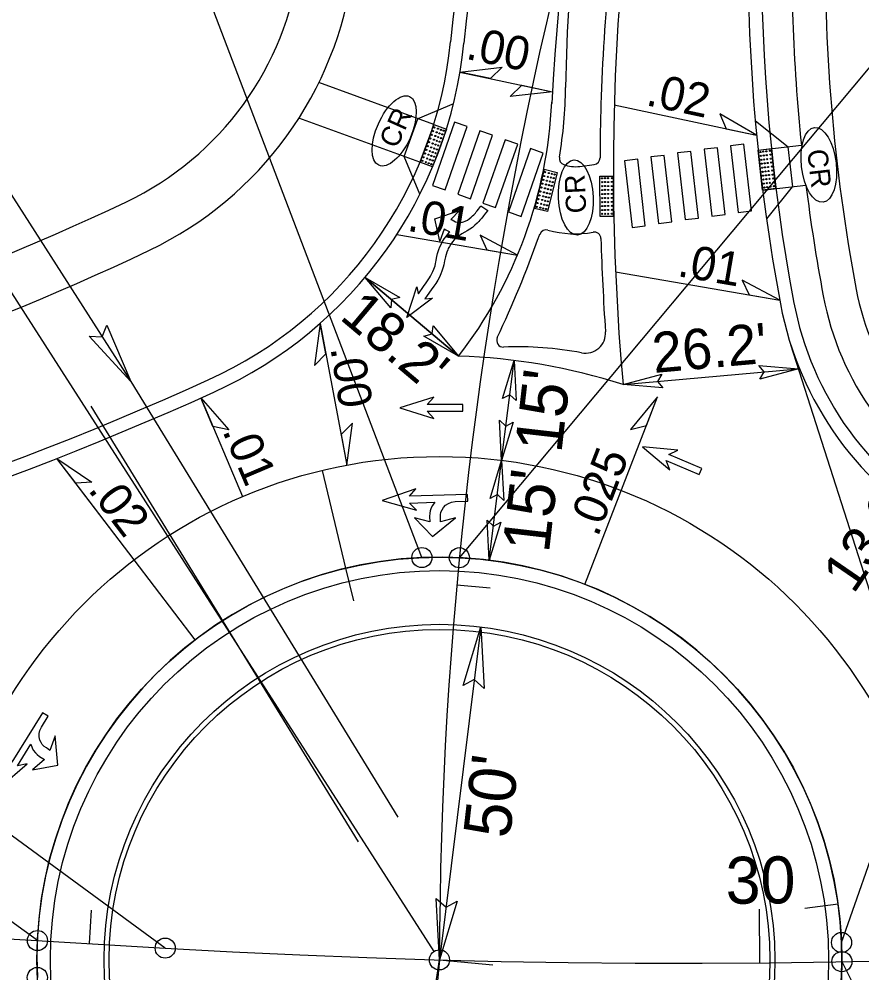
# Model space of a CAD drawing. Extents: x 2010838 to 2015151, y 441905 to 447792.
# Drawn here: x 2013125.6 to 2013251.3, y 444916.5 to 445058.6 of the extents above; entities that cross this region are included whole.
import ezdxf

# ---------------------------------------------------------------- set-up
doc = ezdxf.new("R2010")
doc.units = 0
for name, color, linetype in [('1-BUFFER', 7, 'Continuous'), ('A-Wall-Abov', 7, 'Continuous'), ('A-Wall-Blow', 7, 'Continuous'), ('A-Wall-Comp', 7, 'Continuous'), ('C-Building', 7, 'Continuous'), ('C-CURB STOPS', 7, 'Continuous'), ('C-EOP 1', 7, 'Continuous'), ('C-Grave Plots', 7, 'Continuous'), ('CLRD', 7, 'Continuous'), ('DEED', 7, 'Continuous'), ('Default_10ft_LIDAR_Contou', 7, 'Continuous'), ('Default_2FT_LIDAR_Contour', 7, 'Continuous'), ('HATCH', 7, 'Continuous'), ('s-Existing Major', 7, 'Continuous'), ('S-Existing Minor', 7, 'Continuous'), ('S-overhead electric', 7, 'Continuous'), ('TEXT-LG', 7, 'Continuous'), ('TEXT-MED', 7, 'Continuous'), ('X3', 7, 'Continuous'), ('X4', 7, 'Continuous')]:
    doc.layers.add(name, color=color, linetype=linetype)

msp = doc.modelspace()

# ---------------------------------------------------------------- linework, layer by layer
at = {"layer": '1-BUFFER'}
for centre, radius, start, end in [((2013121.83, 445072.89), 46, 295.4749, 352.5631), ((2013121.83, 445072.89), 54, 295.4749, 352.5631), ((2012983.33, 445363.58), 368, 266.6264, 295.4749), ((2012983.33, 445363.58), 376, 266.6264, 295.4749)]:
    msp.add_arc(centre, radius, start, end, dxfattribs=at)
at = {"layer": 'A-Wall-Abov'}
for points in [[(2013183.41, 445014.1), (2013184.89, 445018.66), (2013185.13, 445017.69), (2013185.14, 445017.65), (2013185.91, 445018.73), (2013186.3, 445019.29), (2013186.48, 445019.55), (2013186.78, 445020.01), (2013186.96, 445020.28), (2013187.06, 445020.46), (2013187.31, 445020.95), (2013187.45, 445021.29), (2013187.54, 445021.54), (2013187.62, 445021.83), (2013187.7, 445022.14), (2013187.75, 445022.34), (2013187.81, 445022.64), (2013187.91, 445023.22), (2013188.01, 445023.64), (2013188.1, 445023.94), (2013188.19, 445024.23), (2013188.36, 445024.65), (2013188.52, 445025), (2013188.74, 445025.43), (2013189, 445025.83), (2013189.23, 445026.15), (2013189.41, 445026.38), (2013189.55, 445026.54), (2013189.85, 445026.85), (2013189.67, 445026.92), (2013189.4, 445027.05), (2013189.24, 445027.13), (2013188.98, 445027.28), (2013188.34, 445025.46), (2013187.57, 445028.81), (2013191.26, 445030.05), (2013190, 445028.73), (2013190.16, 445028.64), (2013190.44, 445028.5), (2013190.69, 445028.38), (2013190.93, 445028.31), (2013191.18, 445028.26), (2013191.39, 445028.25), (2013191.71, 445028.29), (2013191.89, 445028.34), (2013192.12, 445028.44), (2013192.47, 445028.62), (2013192.73, 445028.81), (2013192.99, 445029.04), (2013193.21, 445029.24), (2013193.41, 445029.43), (2013193.63, 445029.67), (2013193.77, 445029.83), (2013193.92, 445030.01), (2013194.1, 445030.24), (2013194.24, 445030.43), (2013194.4, 445030.66), (2013194.47, 445030.77), (2013195.47, 445030.06), (2013195.17, 445029.65), (2013194.87, 445029.27), (2013194.6, 445028.93), (2013194.32, 445028.61), (2013194.13, 445028.39), (2013193.9, 445028.15), (2013193.58, 445027.85), (2013193.21, 445027.54), (2013192.82, 445027.26), (2013192.43, 445027.03), (2013192.05, 445026.83), (2013191.64, 445026.58), (2013191.25, 445026.32), (2013190.78, 445025.95), (2013190.47, 445025.67), (2013190.22, 445025.37), (2013189.96, 445025.02), (2013189.76, 445024.7), (2013189.6, 445024.39), (2013189.51, 445024.17), (2013189.39, 445023.82), (2013189.19, 445023.15), (2013189.03, 445022.53), (2013188.91, 445021.98), (2013188.84, 445021.63), (2013188.8, 445021.45), (2013188.66, 445021), (2013188.51, 445020.6), (2013188.29, 445020.14), (2013188.03, 445019.68), (2013187.74, 445019.2), (2013187.45, 445018.79), (2013187.06, 445018.24), (2013186.45, 445017.37), (2013186.12, 445016.9), (2013187.22, 445017)], [(2013187.45, 444999.08), (2013186.45, 445000.16), (2013191.78, 445000.15), (2013191.78, 445001.15), (2013186.45, 445001.16), (2013187.45, 445002.24), (2013182.37, 445000.66)], [(2013222.6, 444991.41), (2013222.1, 444992.8), (2013227, 444990.7), (2013227.4, 444991.62), (2013222.49, 444993.72), (2013223.84, 444994.32), (2013218.55, 444994.86)], [(2013192.47, 444987.74), (2013183.81, 444987.47), (2013184.78, 444988.59), (2013179.74, 444986.85), (2013184.87, 444985.42), (2013183.84, 444986.47), (2013187.61, 444986.59), (2013187.26, 444986.12), (2013187.06, 444985.76), (2013186.92, 444985.31), (2013186.85, 444984.94), (2013186.8, 444984.47), (2013186.84, 444983.65), (2013184.57, 444984.25), (2013187.24, 444981.49), (2013190.66, 444984.26), (2013188.43, 444983.69), (2013188.42, 444984.34), (2013188.42, 444984.73), (2013188.51, 444985.12), (2013188.67, 444985.46), (2013188.86, 444985.8), (2013189.2, 444986.15), (2013189.62, 444986.41), (2013190.08, 444986.59), (2013190.61, 444986.69), (2013192.5, 444986.74)]]:
    msp.add_lwpolyline(points, close=True, dxfattribs=at)
msp.add_lwpolyline([(2013122.78, 444944.14), (2013126.81, 444947.62), (2013125.37, 444947.34), (2013127.36, 444950.55), (2013127.55, 444949.99), (2013127.74, 444949.63), (2013128.04, 444949.26), (2013128.31, 444949), (2013128.67, 444948.7), (2013129.38, 444948.28), (2013127.63, 444946.72), (2013131.4, 444947.42), (2013130.98, 444951.8), (2013130.22, 444949.62), (2013129.68, 444949.98), (2013129.36, 444950.19), (2013129.08, 444950.48), (2013128.89, 444950.81), (2013128.71, 444951.15), (2013128.61, 444951.62), (2013128.62, 444952.13), (2013128.73, 444952.6), (2013128.94, 444953.1), (2013129.95, 444954.7), (2013129.1, 444955.23), (2013124.52, 444947.87)], dxfattribs=at)
at = {"layer": 'A-Wall-Blow'}
for p, q in [((2013191.34, 445050.68), (2013205.11, 445047.75)), ((2013214.35, 445045.78), (2013235.55, 445041.27)), ((2013181.94, 445026.49), (2013199.91, 445023.41)), ((2013214.54, 445020.89), (2013239, 445016.69)), ((2013170.51, 445013.24), (2013174.47, 444992.11)), ((2013152.69, 445002.12), (2013158.94, 444987.42)), ((2013209.96, 444974.34), (2013220.8, 445002.31)), ((2013142.78, 444978.02), (2013131.25, 444993.12)), ((2013170.8, 444991.33), (2013174.3, 444976.74)), ((2013151.88, 444966.09), (2013133.68, 444989.94))]:
    msp.add_line(p, q, dxfattribs=at)
at = {"layer": 'A-Wall-Comp'}
for points in [[(2013191.34, 445050.68), (2013197.63, 445051.39), (2013195.87, 445049.72)], [(2013205.11, 445047.75), (2013198.82, 445047.04), (2013200.58, 445048.71)], [(2013235.55, 445041.27), (2013230.1, 445044.47), (2013231.03, 445042.23)], [(2013199.91, 445023.41), (2013194.34, 445026.39), (2013195.35, 445024.19)], [(2013239, 445016.69), (2013233.43, 445019.68), (2013234.45, 445017.47)], [(2013170.51, 445013.24), (2013169.65, 445006.98), (2013171.36, 445008.7)], [(2013152.69, 445002.12), (2013156.88, 444997.38), (2013154.5, 444997.86)], [(2013220.8, 445002.31), (2013216.77, 444997.44), (2013219.13, 444998)], [(2013174.47, 444992.11), (2013175.33, 444998.38), (2013173.61, 444996.66)], [(2013131.25, 444993.12), (2013136.48, 444989.56), (2013134.06, 444989.44)]]:
    msp.add_lwpolyline(points, close=True, dxfattribs=at)
at = {"layer": 'C-Building'}
for p, q in [((2013174.3, 444976.74), (2013175.46, 444971.88)), ((2013190.87, 444974.28), (2013195.85, 444973.83)), ((2013136.12, 444920.83), (2013136.41, 444925.82)), ((2013136.12, 444920.83), (2013136.41, 444925.82)), ((2013247.7, 444926.73), (2013242.75, 444926.04))]:
    msp.add_line(p, q, dxfattribs=at)
at = {"layer": 'C-CURB STOPS'}
msp.add_line((2013209.19, 445036.62), (2013211.35, 445036.91), dxfattribs=at)
msp.add_circle((2013188.28, 444918.4), 58, dxfattribs=at)
for centre, radius, start, end in [((2013432.07, 445045.8), 225, 165.9339, 179.3398), ((2013462.25, 445038.81), 250, 169.3674, 178.3799), ((2013138.34, 445049.19), 68.75, 350.6175, 359.3398), ((2013563.46, 445035.95), 351.25, 178.3799, 179.6818), ((2013207.16, 445037.82), 1, 170.6175, 250.0381), ((2013211.22, 445037.9), 1, 277.6992, 359.6818), ((2013208.52, 445041.58), 5, 250.0381, 277.6992), ((2013138.34, 445049.19), 68.75, 340.2993, 340.736), ((2013204.19, 445026.17), 1, 74.2692, 160.736), ((2013208.52, 445041.58), 15, 254.2692, 280.1946), ((2013211.36, 445025.83), 1, 1.6461, 100.1946), ((2013047.54, 445081.7), 165.19, 334.7102, 340.2993), ((2013563.46, 445035.95), 351.25, 181.6461, 183.91), ((2013197.81, 445010.7), 1, 154.7102, 272.3391), ((2013210.04, 445011.79), 3, 259.2155, 3.91), ((2013199.93, 444958.74), 51, 79.2155, 92.3391)]:
    msp.add_arc(centre, radius, start, end, dxfattribs=at)
at = {"layer": 'C-EOP 1'}
for p, q in [((2013236.05, 444917.96), (2013235.98, 444925.96)), ((2013236.05, 444917.96), (2013235.98, 444925.96)), ((2013188.28, 444918.4), (2013196.25, 444917.68))]:
    msp.add_line(p, q, dxfattribs=at)
at = {"layer": 'CLRD'}
for p, q in [((2011239.41, 445032.63), (2013147.4, 444920.16)), ((2013188.28, 444918.4), (2013178.69, 444811.64))]:
    msp.add_line(p, q, dxfattribs=at)
for centre, radius, start, end in [((2013223.9, 446217.91), 1300, 266.62643, 322.2051), ((2013818.28, 444917.2), 630, 153.45572, 179.8908), ((2013188.28, 444918.4), 60, 92.4922, 182.4922), ((2013188.28, 444918.4), 60, 2.4922, 92.4922), ((2013188.28, 444918.4), 60, 272.4922, 2.4922)]:
    msp.add_arc(centre, radius, start, end, dxfattribs=at)
at = {"layer": 'DEED'}
for radius in [50, 49.25]:
    msp.add_circle((2013188.28, 444918.4), radius, dxfattribs=at)
at = {"layer": 'Default_10ft_LIDAR_Contou'}
for p, q in [((2013185.67, 444978.34), (2013129.37, 445126.14)), ((2013187.48, 444919.66), (2013069.3, 445103.84)), ((2013191.25, 444978.32), (2013276.3, 445079.96)), ((2013147.4, 444920.16), (2012935.98, 445074.74)), ((2013128.35, 444921.28), (2012936.75, 445060.1)), ((2013248.22, 444921), (2013289.46, 445039.08)), ((2013248.28, 444918.14), (2013322.3, 444771.2))]:
    msp.add_line(p, q, dxfattribs=at)
for centre in [(2013185.67, 444978.34), (2013191.25, 444978.32), (2013128.35, 444921.28), (2013248.22, 444921), (2013147.4, 444920.16), (2013188.28, 444918.4), (2013188.28, 444918.4), (2013188.28, 444918.4), (2013248.28, 444918.14), (2013128.34, 444915.79)]:
    msp.add_circle(centre, 1.5, dxfattribs=at)
at = {"layer": 'HATCH'}
for p, q in [((2013190.52, 445043.23), (2013187.22, 445033.79)), ((2013189.11, 445033.13), (2013192.41, 445042.57)), ((2013192.41, 445042.57), (2013190.52, 445043.23)), ((2013194.3, 445041.91), (2013191, 445032.47)), ((2013196.18, 445041.25), (2013194.3, 445041.91)), ((2013192.89, 445031.81), (2013196.18, 445041.25)), ((2013198.07, 445040.59), (2013194.77, 445031.15)), ((2013199.96, 445039.93), (2013198.07, 445040.59)), ((2013196.66, 445030.49), (2013199.96, 445039.93)), ((2013201.85, 445039.27), (2013198.55, 445029.83)), ((2013203.74, 445038.61), (2013201.85, 445039.27)), ((2013229.71, 445039.39), (2013227.72, 445039.17)), ((2013227.72, 445039.17), (2013228.87, 445029.23)), ((2013230.85, 445029.46), (2013229.71, 445039.39)), ((2013233.68, 445039.93), (2013231.69, 445039.7)), ((2013231.69, 445039.7), (2013232.83, 445029.77)), ((2013234.82, 445030), (2013233.68, 445039.93)), ((2013200.44, 445029.17), (2013203.74, 445038.61)), ((2013217.83, 445037.69), (2013215.85, 445037.46)), ((2013218.97, 445027.75), (2013217.83, 445037.69)), ((2013221.79, 445038.27), (2013219.8, 445038.05)), ((2013219.8, 445038.05), (2013220.94, 445028.11)), ((2013222.93, 445028.34), (2013221.79, 445038.27)), ((2013225.75, 445038.86), (2013223.76, 445038.63)), ((2013223.76, 445038.63), (2013224.9, 445028.7)), ((2013226.89, 445028.92), (2013225.75, 445038.86)), ((2013215.85, 445037.46), (2013216.99, 445027.53)), ((2013187.22, 445033.79), (2013189.11, 445033.13)), ((2013191, 445032.47), (2013192.89, 445031.81)), ((2013194.77, 445031.15), (2013196.66, 445030.49)), ((2013198.55, 445029.83), (2013200.44, 445029.17)), ((2013228.87, 445029.23), (2013230.85, 445029.46)), ((2013232.83, 445029.77), (2013234.82, 445030)), ((2013216.99, 445027.53), (2013218.97, 445027.75)), ((2013220.94, 445028.11), (2013222.93, 445028.34)), ((2013224.9, 445028.7), (2013226.89, 445028.92)), ((2013191.14, 445008.35), (2013177.2, 445020.08)), ((2013260.92, 444946.8), (2013240.66, 445010.03))]:
    msp.add_line(p, q, dxfattribs=at)
msp.add_circle((2013188.28, 444918.4), 75, dxfattribs=at)
at = {"layer": 's-Existing Major'}
for points in [[(2013181.03, 445015.55), (2013177.2, 445020.08), (2013182.37, 445017.09), (2013181.13, 445016.78)], [(2013138.72, 445012.98), (2013142.27, 445004.57), (2013136.04, 445011.33), (2013138.01, 445011.22)], [(2013187.32, 445012.89), (2013191.14, 445008.35), (2013185.97, 445011.34), (2013187.21, 445011.66)], [(2013197.68, 445002.02), (2013199.41, 445007.71), (2013199.71, 445001.74), (2013198.77, 445002.61)], [(2013235.89, 445006.95), (2013241.81, 445006.46), (2013236.04, 445004.9), (2013236.69, 445006.01)], [(2013221.58, 445003.65), (2013215.66, 445004.13), (2013221.43, 445005.69), (2013220.78, 445004.59)], [(2013199.27, 444998.5), (2013197.55, 444992.82), (2013197.25, 444998.79), (2013198.19, 444997.92)], [(2013195.83, 444987.14), (2013197.55, 444992.82), (2013197.86, 444986.85), (2013196.92, 444987.72)], [(2013197.42, 444983.62), (2013195.7, 444977.94), (2013195.39, 444983.9), (2013196.33, 444983.03)], [(2013191.81, 444959.27), (2013194.46, 444968.01), (2013194.93, 444958.83), (2013193.48, 444960.17)], [(2013190.93, 444927.14), (2013188.28, 444918.4), (2013187.81, 444927.57), (2013189.26, 444926.24)]]:
    msp.add_lwpolyline(points, close=True, dxfattribs=at)
at = {"layer": 'S-Existing Minor'}
for p, q in [((2013027.47, 445183.82), (2013142.27, 445004.57)), ((2013177.2, 445020.08), (2013191.14, 445008.35)), ((2013197.55, 444992.82), (2013199.41, 445007.71)), ((2013215.66, 445004.13), (2013241.81, 445006.46)), ((2013195.7, 444977.94), (2013197.55, 444992.82)), ((2013194.46, 444968.01), (2013188.28, 444918.4)), ((2013174.66, 444829.43), (2013188.28, 444918.4))]:
    msp.add_line(p, q, dxfattribs=at)
at = {"layer": 'S-overhead electric'}
msp.add_circle((2013188.28, 444918.4), 60, dxfattribs=at)
for centre, radius, start, end in [((2013484.7, 445032.62), 280, 153.4557, 177.261), ((2013481.49, 445026.2), 291, 153.4557, 174.3271), ((2013563.46, 445035.95), 349.25, 165.0914, 185.2272), ((2013514.28, 445067.92), 280, 168.5475, 190.6549), ((2013128.23, 445061.29), 64, 294.3799, 354.3271), ((2013138.34, 445049.19), 66.75, 322.2815, 357.4094), ((2013288.24, 445025.39), 50, 190.6549, 241.0711), ((2013188.28, 444918.4), 90, 72.2859, 88.1766), ((2012952.38, 445449.3), 490, 266.6264, 294.3799)]:
    msp.add_arc(centre, radius, start, end, dxfattribs=at)
at = {"layer": 'TEXT-LG'}
for p, q in [((2013187.43, 445042.87), (2013170.31, 445049.11)), ((2013190.37, 445045.96), (2013185.07, 445043.73)), ((2013185.37, 445037.24), (2013167.32, 445043.81)), ((2013183.02, 445038.09), (2013185.07, 445043.73)), ((2013235.4, 445043.43), (2013240.27, 445039.56)), ((2013187.43, 445042.87), (2013185.38, 445037.23)), ((2013189.31, 445042.19), (2013187.26, 445036.55)), ((2013187.43, 445042.87), (2013189.31, 445042.19)), ((2013235.78, 445039.05), (2013242.23, 445039.78)), ((2013235.78, 445039.05), (2013237.77, 445039.27)), ((2013236.46, 445033.08), (2013235.78, 445039.05)), ((2013238.45, 445033.31), (2013237.77, 445039.27)), ((2013240.95, 445033.6), (2013240.27, 445039.56)), ((2013185.38, 445032.48), (2013183.02, 445038.09)), ((2013187.26, 445036.55), (2013185.38, 445037.23)), ((2013203.88, 445036.19), (2013202.45, 445030.36)), ((2013203.88, 445036.19), (2013205.83, 445035.71)), ((2013205.83, 445035.71), (2013204.4, 445029.89)), ((2013212.21, 445035.17), (2013214.21, 445035.18)), ((2013212.25, 445029.17), (2013212.21, 445035.17)), ((2013214.25, 445029.18), (2013214.21, 445035.18)), ((2013236.46, 445033.08), (2013242.91, 445033.82)), ((2013237.07, 445028.79), (2013240.89, 445033.59)), ((2013238.45, 445033.31), (2013236.46, 445033.08)), ((2013204.4, 445029.89), (2013202.45, 445030.36)), ((2013214.25, 445029.18), (2013212.25, 445029.17))]:
    msp.add_line(p, q, dxfattribs=at)
for centre in [(2013187.34, 445041.88), (2013187.54, 445042.42), (2013188.07, 445042.24), (2013188.5, 445042.07), (2013188.9, 445041.94), (2013186.94, 445040.78), (2013187.14, 445041.32), (2013187.46, 445040.6), (2013187.66, 445041.14), (2013187.87, 445041.7), (2013187.89, 445040.43), (2013188.09, 445040.97), (2013188.3, 445041.54), (2013188.5, 445040.83), (2013188.7, 445041.4), (2013186.32, 445039.08), (2013186.53, 445039.64), (2013186.73, 445040.22), (2013187.05, 445039.46), (2013187.26, 445040.03), (2013187.48, 445039.3), (2013187.69, 445039.87), (2013187.89, 445039.16), (2013188.09, 445039.73), (2013188.3, 445040.3), (2013237.56, 445038.94), (2013185.91, 445037.98), (2013186.12, 445038.54), (2013186.44, 445037.8), (2013186.65, 445038.36), (2013186.84, 445038.9), (2013186.87, 445037.63), (2013187.08, 445038.2), (2013187.27, 445038.73), (2013187.28, 445037.49), (2013187.48, 445038.06), (2013187.68, 445038.6), (2013236.13, 445038.76), (2013236.19, 445038.19), (2013236.26, 445037.6), (2013236.55, 445038.82), (2013236.62, 445038.25), (2013236.68, 445037.66), (2013237.01, 445038.87), (2013237.07, 445038.3), (2013237.14, 445037.7), (2013237.62, 445038.37), (2013237.69, 445037.77), (2013185.72, 445037.44), (2013186.24, 445037.26), (2013186.67, 445037.09), (2013187.08, 445036.96), (2013236.32, 445037.03), (2013236.39, 445036.43), (2013236.75, 445037.08), (2013236.81, 445036.49), (2013237.2, 445037.13), (2013237.27, 445036.53), (2013237.75, 445037.2), (2013237.82, 445036.61), (2013203.9, 445035.19), (2013204.04, 445035.75), (2013204.44, 445035.07), (2013204.58, 445035.63), (2013204.89, 445034.96), (2013205.03, 445035.51), (2013205.31, 445034.86), (2013205.45, 445035.42), (2013212.52, 445034.85), (2013212.95, 445034.86), (2013213.41, 445034.86), (2013213.97, 445034.87), (2013236.46, 445035.82), (2013236.52, 445035.23), (2013236.59, 445034.66), (2013236.88, 445035.88), (2013236.95, 445035.29), (2013237.01, 445034.72), (2013237.34, 445035.93), (2013237.41, 445035.33), (2013237.47, 445034.76), (2013237.89, 445036), (2013237.96, 445035.4), (2013238.02, 445034.83), (2013203.48, 445033.47), (2013203.62, 445034.06), (2013203.76, 445034.61), (2013204.02, 445033.35), (2013204.16, 445033.93), (2013204.3, 445034.49), (2013204.46, 445033.23), (2013204.61, 445033.82), (2013204.74, 445034.37), (2013205.02, 445033.72), (2013205.16, 445034.28), (2013212.53, 445034.28), (2013212.53, 445033.68), (2013212.96, 445034.29), (2013212.96, 445033.69), (2013213.42, 445034.29), (2013213.42, 445033.69), (2013213.97, 445034.3), (2013213.97, 445033.7), (2013236.65, 445034.06), (2013236.72, 445033.49), (2013237.08, 445034.12), (2013237.14, 445033.55), (2013237.54, 445034.17), (2013237.6, 445033.6), (2013238.09, 445034.24), (2013238.15, 445033.67), (2013203.19, 445032.3), (2013203.33, 445032.88), (2013203.73, 445032.17), (2013203.87, 445032.76), (2013204.17, 445032.06), (2013204.32, 445032.64), (2013204.59, 445031.97), (2013204.74, 445032.55), (2013204.88, 445033.14), (2013212.53, 445033.1), (2013212.53, 445032.5), (2013212.54, 445031.89), (2013212.96, 445033.12), (2013212.96, 445032.52), (2013212.97, 445031.91), (2013213.42, 445033.11), (2013213.42, 445032.51), (2013213.43, 445031.9), (2013213.97, 445033.12), (2013213.98, 445032.52), (2013213.98, 445031.92), (2013202.77, 445030.6), (2013202.91, 445031.16), (2013203.05, 445031.74), (2013203.31, 445030.48), (2013203.45, 445031.04), (2013203.59, 445031.62), (2013203.89, 445030.92), (2013204.04, 445031.5), (2013204.31, 445030.83), (2013204.45, 445031.41), (2013212.54, 445031.29), (2013212.54, 445030.72), (2013212.97, 445031.31), (2013212.97, 445030.73), (2013213.43, 445031.3), (2013213.43, 445030.73), (2013213.98, 445031.32), (2013213.99, 445030.74), (2013203.75, 445030.36), (2013204.17, 445030.27), (2013212.54, 445030.12), (2013212.55, 445029.55), (2013212.97, 445030.13), (2013212.98, 445029.56), (2013213.43, 445030.13), (2013213.44, 445029.56), (2013213.99, 445030.14), (2013213.99, 445029.57)]:
    msp.add_circle(centre, 0.0869, dxfattribs=at)
for centre, radius, start, end in [((2013514.28, 445067.92), 273.5, 178.1336, 185.9047), ((2013514.28, 445067.92), 268.5, 178.8864, 190.6549), ((2013514.28, 445067.92), 273.5, 187.1616, 190.6549), ((2013288.24, 445025.39), 38.5, 190.6549, 241.0711), ((2013288.24, 445025.39), 43.5, 190.6549, 241.0711)]:
    msp.add_arc(centre, radius, start, end, dxfattribs=at)
at = {"layer": 'TEXT-MED'}
for centre, radius, start, end in [((2013481.49, 445026.2), 293, 153.4557, 174.3271), ((2013514.28, 445067.92), 278, 168.5475, 190.6549), ((2013128.23, 445061.29), 62, 294.3799, 354.3271), ((2013288.24, 445025.39), 48, 190.6549, 241.0711), ((2012952.38, 445449.3), 488, 266.6264, 294.3799)]:
    msp.add_arc(centre, radius, start, end, dxfattribs=at)
at = {"layer": 'X3'}
for p, q in [((2013142.27, 445004.57), (2013182.09, 444939.66)), ((2013136.32, 445000.92), (2013176.14, 444936.01))]:
    msp.add_line(p, q, dxfattribs=at)
at = {"layer": 'X4'}
for centre, major_axis in [((2013181.54, 445041.91), (2.29, 5.12)), ((2013244.83, 445036.85), (0.63, -5.57)), ((2013208.6, 445031.98), (-0.26, 5.6))]:
    msp.add_ellipse(centre, major_axis=major_axis, ratio=0.462467, dxfattribs=at)

# ---------------------------------------------------------------- texts
at = {"layer": 'A-Wall-Blow'}
for s, rotation, p in [('.00', 347.9803, (2013192.06, 445052.68)), ('.02', 347.9803, (2013218.91, 445045.77)), ('.01', 350.2539, (2013183.33, 445027.05)), ('.01', 350.2539, (2013223.61, 445020.29)), ('.00', 278.7035, (2013172.02, 445009.55)), ('.01', 293.0274, (2013155.87, 444997.22)), ('.025', 68.8148, (2013211.87, 444981.28)), ('.02', 307.3514, (2013135.78, 444988.42))]:
    msp.add_text(s, height=5, rotation=rotation, dxfattribs=at).set_placement(p)
at = {"layer": 'C-Grave Plots'}
for s, height, rotation, p in [("18.2'", 6, 319.9206, (2013173.24, 445013.98)), ("26.2'", 6, 5.1016, (2013220.27, 445005.84)), ("15'", 7, 83.4264, (2013206.45, 444993.77)), ("15'", 7, 83.4264, (2013204.59, 444978.89)), ("13.3'", 6, 55.581, (2013250, 444972.78)), ("50'", 7, 83.4264, (2013198.76, 444936.36))]:
    msp.add_text(s, height=height, rotation=rotation, dxfattribs=at).set_placement(p)
at = {"layer": 'Default_2FT_LIDAR_Contour'}
msp.add_text('30', height=7, rotation=0.5355, dxfattribs=at).set_placement((2013230.97, 444926.75))
at = {"layer": 'X4'}
for rotation, p in [(65.8536, (2013181.92, 445039.15)), (276.4985, (2013243.09, 445039.03)), (92.6405, (2013210.18, 445029.7))]:
    msp.add_text('CR', height=3, rotation=rotation, dxfattribs=at).set_placement(p)

doc.saveas('drawing.dxf')
